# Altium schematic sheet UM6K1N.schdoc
size 127 x 101 mm
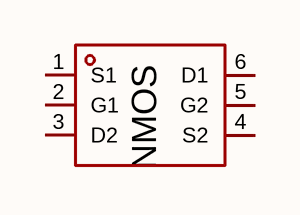
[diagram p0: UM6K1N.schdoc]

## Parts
Q?  um6k1n  [SOT-363_L2.1-W1.3-P0.65-LS2.2-BL]  (value not drawn)

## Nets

Not connected (* = marked no-connect by the designer): Q? 1(S1) 2(G1) 3(D2) 4(S2) 5(G2) 6(D1)

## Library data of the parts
Q? = um6k1n: 数量:2个N沟道;漏源电压(Vdss):30V;连续漏极电流(Id):100mA;导通电阻(RDS(on)):4Ω@4V；6Ω@2.5V;耗散功率(Pd):150mW;阈值电压(Vgs(th)):1.5V;; Manufacturer: CJ(江苏长电/长晶); AddInBom: yes; ModelId: 3242230cf6ca43ce877eb5133a399b63; ModelTransform: 80.709,86.614,0,0,0,0,0,0,0; Number: 2个N沟道; Drain to Source Voltage: 30V; Current - Continuous Drain(Id): 100mA; Pd - Power Dissipation: 150mW; Gate Threshold Voltage (Vgs(th)): 1.5V; Input Capacitance(Ciss): 13pF; Reverse Transfer Capacitance (Crss@Vds): 4pF; Type: N沟道; Output Capacitance(Coss): 9pF; Vgs: ±20V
